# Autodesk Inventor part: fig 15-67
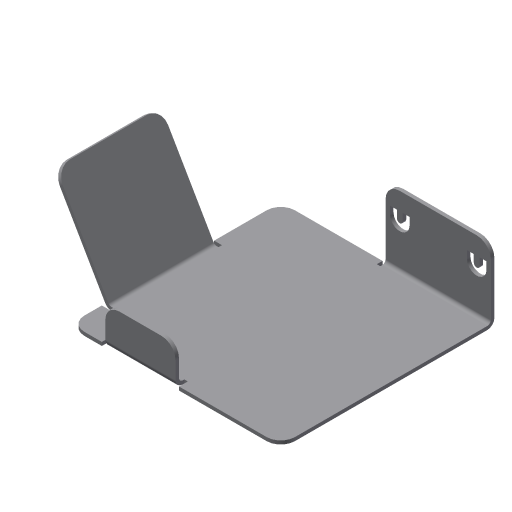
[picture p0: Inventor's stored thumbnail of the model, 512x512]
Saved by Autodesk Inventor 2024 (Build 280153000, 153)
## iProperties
Shininess: 77.0
Angle Display Precision: 2
Document Length Units: 11269
Document Angle Units: 11279
Document Time Units: 11290
Document Mass Units: 11283
Document Length Units Precision: 3
Document Angle Units Precision: 2
Created: 2002-04
Part Number: fig 15-67
Document SubType Name: Sheet Metal
Density: 1 g/cm^3
Sheet Metal Rule: Default
Material: Generic
Appearance: Default
Density: 0.0
Volumn: 0.0
Area: 0.0
PropertySet Name: Model Information
Control State: 0
Master: False
Checked Out: False
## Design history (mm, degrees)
node "Face1"
  sketch "Sketch1"
    geometry: L1 (12.647, 25.882)-(12.647, -14.118); L2 (12.647, -14.118)-(-17.353, -14.118); L3 (-17.353, -14.118)-(-17.353, 15.882); L4 (-17.353, 15.882)-(-2.353, 15.882); L5 (-2.353, 15.882)-(-2.353, 25.882); L6 (-2.353, 25.882)-(12.647, 25.882); 1 further point
    constraints: 12 end point, 4 parallel, 1 perpendicular
    dimensions: "d5" = 30 distance of L2.end L3.end; "d6" = 10 distance of L4.end L5.end; "d7" = 15 distance of L3.end L4.end; "d25" = 15 distance of L5.end L1.start
sketch "Sketch3"
  geometry: L1 (10, -15)-(10, 0)
  constraints: 2 end point
feature "Fold3" sketch "Sketch3" dims "d26" = 0.5 (= BendRadius), "d27" = 90 deg, "d28" = 0.5 (= BendRadius), "d96" = 0.5 (= BendReliefWidth), "d97" = 0.25 (= BendReliefDepth), "d98" = 1 (= MinimumRemnant), "d108" = 0.5 (= Thickness), "SeamGap" = 0.01
node "Flange2"
sketch "Sketch6"
  geometry: L1 (-6.914, 3.413)-(-5.843, 3.413); L2 (-5.843, 0.624)-(-6.914, 0.624); L3 (-6.914, 2.432)-(-5.843, 2.432); L4 (-5.843, 1.605)-(-6.914, 1.605); L5 (-6.914, 0.624)-(-6.914, 1.605); L6 (-6.914, 2.432)-(-6.914, 3.413); L7 (-6.914, 12.568)-(-6.914, 11.587); L8 (-6.914, 14.376)-(-6.914, 13.395); L9 (-6.914, 11.587)-(-5.843, 11.587); L10 (-5.843, 14.376)-(-6.914, 14.376); L11 (-6.914, 12.568)-(-5.843, 12.568); L12 (-5.843, 13.395)-(-6.914, 13.395); A1 r 1.394 centre (-5.843, 2.018) between (-5.843, 0.624) and (-5.843, 3.413); A2 r 0.413 centre (-5.843, 2.018) between (-5.843, 1.605) and (-5.843, 2.432); A3 r 1.394 centre (-5.843, 12.982) between (-5.843, 11.587) and (-5.843, 14.376); A4 r 0.413 centre (-5.843, 12.982) between (-5.843, 12.568) and (-5.843, 13.395)
  constraints: 24 end point, 8 point on circle, 4 centre point, 3 equal length, 1 perpendicular
cut "Cut1" sketch "Sketch6" dims "d49" = 0.5 (= Thickness), "d50" = 0
node "Flange3"
feature "Corner Round2" dims "d107" = 2
body "Solid1"
face "Plate1" dims "d108" = 0.5 (= Thickness)
sketch "Sketch5"
  geometry: L1 (20, 0)-(5, 0); L2 (5, 0)-(5, 15); L3 (5, 15)-(20, 15); L4 (20, 15)-(20, 0)
  constraints: 8 end point
face "Plate6" dims "d35" = 10, "d36" = 5, "d38" = 15, "d39" = 60 deg, "d40" = 0.5 (= BendRadius), "d108" = 0.5 (= Thickness), "MinimumRemnant" = 1 (= 2 x Thickness), "BendReliefWidth" = 0.5 (= Thickness)
bend "Bend5" dims "d38" = 15, "d39" = 60 deg, "d40" = 0.5 (= BendRadius), "d99" = 0.5 (= BendReliefWidth), "d100" = 0.25 (= BendReliefDepth), "d101" = 1 (= MinimumRemnant), "d108" = 0.5 (= Thickness), "SeamGap" = 0.01, "MinimumRemnant" = 1 (= 2 x Thickness), "BendReliefWidth" = 0.5 (= Thickness), "TransitionRadius" = 0.5 (= BendRadius)
sketch "Sketch7"
  geometry: L1 (25, 0)-(15, 0); L2 (15, 0)-(15, 5); L3 (15, 5)-(25, 5); L4 (25, 5)-(25, 0)
  constraints: 8 end point
face "Plate7" dims "d57" = 5, "d58" = 10, "d60" = 5, "d61" = 90 deg, "d62" = 0.5 (= BendRadius), "d108" = 0.5 (= Thickness), "MinimumRemnant" = 1 (= 2 x Thickness), "BendReliefWidth" = 0.5 (= Thickness)
bend "Bend7" dims "d59" = 0.5 (= BendRadius), "d60" = 5, "d61" = 90 deg, "d62" = 0.5 (= BendRadius), "d102" = 0.5 (= BendReliefWidth), "d103" = 0.25 (= BendReliefDepth), "d104" = 1 (= MinimumRemnant), "d108" = 0.5 (= Thickness), "SeamGap" = 0.01, "MinimumRemnant" = 1 (= 2 x Thickness), "BendReliefWidth" = 0.5 (= Thickness)
other parameters: "Thickness" = 0.5, "BendRadius" = 0.5 (= Thickness), "BendReliefDepth" = 0.25 (= 0.5 x Thickness), "CornerReliefSize" = 2 (= 4 x Thickness), "d0" = 0.5 (= BendRadius), "d13" = 0.5 (= BendRadius), "d31" = 0.5 (= BendRadius), "d37" = 0.5 (= BendRadius), "JacobiRadiusSize" = 0.5 (= Thickness), "GapSize" = 0.5 (= Thickness)
